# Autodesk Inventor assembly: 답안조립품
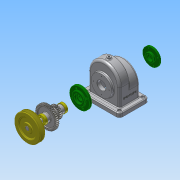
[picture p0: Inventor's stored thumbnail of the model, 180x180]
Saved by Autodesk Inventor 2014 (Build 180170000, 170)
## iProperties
Created: 2017-11
Part Number: 답안조립품
Document SubType Name: Assembly
Designer: sda
Author: sda
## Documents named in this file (12)
- C:\Users\sda\Desktop\471107V1028\답안조립품.iam
- C:\Users\sda\Desktop\471107V1028\본체.ipt
- C:\Users\sda\Desktop\471107V1028\스퍼기어.ipt
- C:\Users\sda\Desktop\471107V1028\축.ipt
- C:\Users\sda\Desktop\471107V1028\키 - 6 x 6 x 22.ipt
- C:\Users\sda\Desktop\471107V1028\베어링 6002.ipt
- C:\Users\sda\Desktop\471107V1028\V-벨트풀리.ipt
- C:\Users\sda\Desktop\471107V1028\멈춤나사 - M4 x 10.ipt
- 멈춤나사 - M4 x 10.ipt
- C:\Users\sda\Desktop\471107V1028\키 - 5 x 5 x 18.ipt
- C:\Users\sda\Desktop\471107V1028\뒤커버.ipt
- C:\Users\sda\Desktop\471107V1028\앞커버.ipt
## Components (1 placed, 1 different names)
1. V-벨트풀리:1 — 플러쉬:1
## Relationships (1: Flush 1)
- 플러쉬:1 [Flush]: V-벨트풀리:1
